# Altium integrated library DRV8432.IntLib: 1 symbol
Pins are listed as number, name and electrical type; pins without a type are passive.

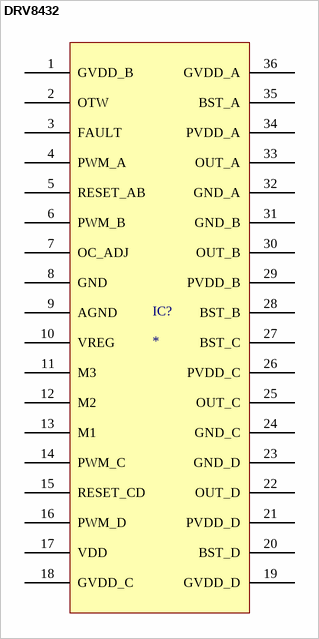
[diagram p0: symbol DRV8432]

## DRV8432
designator IC?
footprint DRV8432
pins: 1 GVDD_B, 2 OTW, 3 FAULT, 4 PWM_A, 5 RESET_AB, 6 PWM_B, 7 OC_ADJ, 8 GND, 9 AGND, 10 VREG, 11 M3, 12 M2, 13 M1, 14 PWM_C, 15 RESET_CD, 16 PWM_D, 17 VDD, 18 GVDD_C, 19 GVDD_D, 20 BST_D, 21 PVDD_D, 22 OUT_D, 23 GND_D, 24 GND_C, 25 OUT_C, 26 PVDD_C, 27 BST_C, 28 BST_B, 29 PVDD_B, 30 OUT_B, 31 GND_B, 32 GND_A, 33 OUT_A, 34 PVDD_A, 35 BST_A, 36 GVDD_A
